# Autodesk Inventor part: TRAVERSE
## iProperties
Created: 2011-01
Part Number: TRAVERSE
Document SubType Name: Modeling
Designer: eric
Density: 1 g/cm^3
Mass: 21.6806 g
Surface Area: 305.415 cm^2
Volume: 21.6806 cm^3
Author: eric
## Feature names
1. Base1
